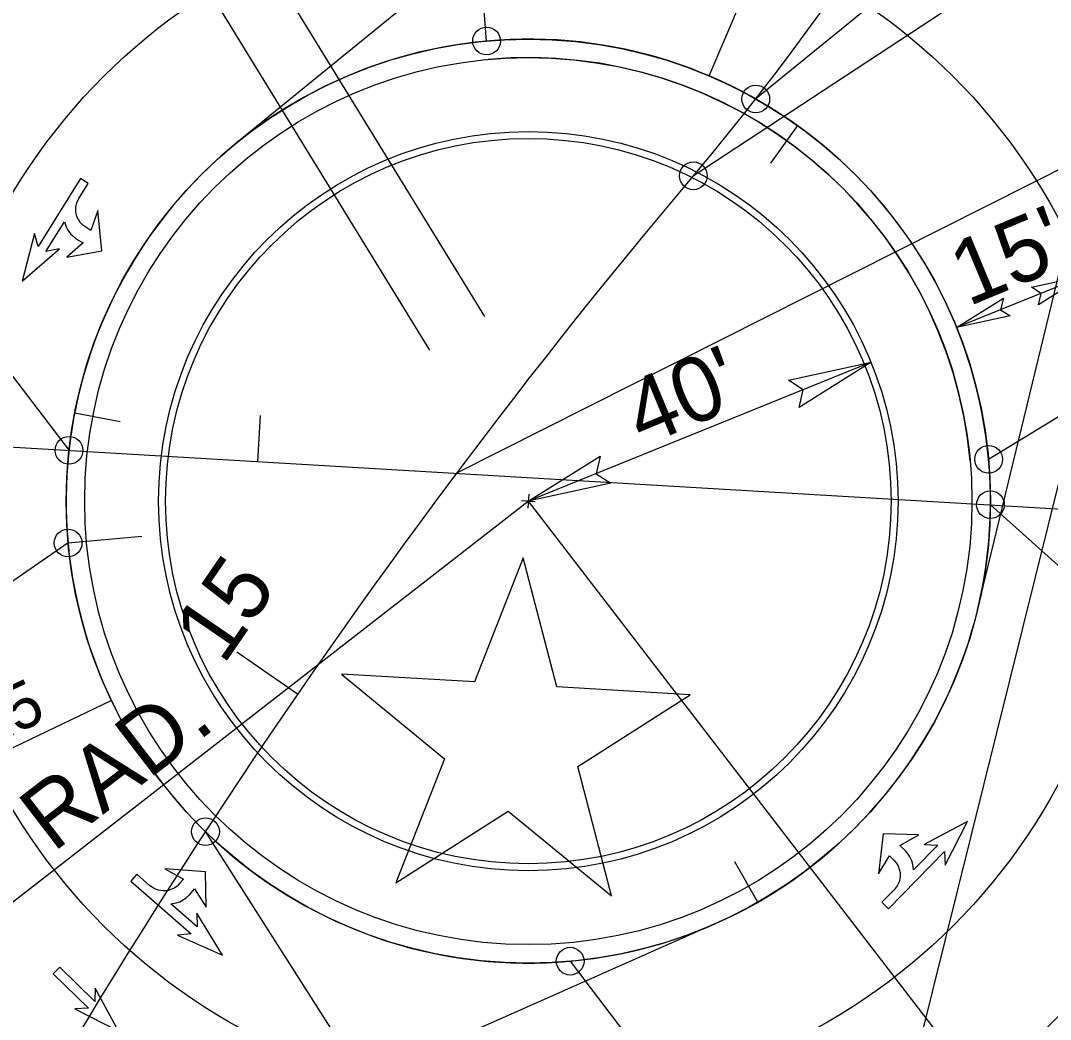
# Model space of a CAD drawing. Extents: x 2010838 to 2015151, y 441905 to 447792.
# Drawn here: x 2011912.5 to 2012023.9, y 444931.1 to 445039.2 of the extents above; entities that cross this region are included whole.
import ezdxf

# ---------------------------------------------------------------- set-up
doc = ezdxf.new("R2010")
doc.units = 0
for name, color, linetype in [('A-Wall-Abov', 7, 'Continuous'), ('A-Wall-Blow', 7, 'Continuous'), ('Block signals', 7, 'Continuous'), ('C-Building', 7, 'Continuous'), ('C-CURB STOPS', 7, 'Continuous'), ('C-EOP 1', 7, 'Continuous'), ('C-Grave Plots', 7, 'Continuous'), ('C-Surface', 7, 'Continuous'), ('CLRD', 7, 'Continuous'), ('Default_10ft_LIDAR_Contou', 7, 'Continuous'), ('Default_2FT_LIDAR_Contour', 7, 'Continuous'), ('HATCH', 7, 'Continuous'), ('s-Existing Major', 7, 'Continuous'), ('S-Existing Minor', 7, 'Continuous'), ('S-overhead electric', 7, 'Continuous'), ('TEXT', 7, 'Continuous'), ('X3', 7, 'Continuous')]:
    doc.layers.add(name, color=color, linetype=linetype)

msp = doc.modelspace()

# ---------------------------------------------------------------- linework, layer by layer
at = {"layer": 'A-Wall-Abov'}
for points in [[(2011919, 445022.07), (2011914.42, 445014.71), (2011914.03, 445016.13), (2011912.69, 445010.98), (2011916.72, 445014.46), (2011915.27, 445014.18), (2011917.26, 445017.38), (2011917.46, 445016.83), (2011917.65, 445016.47), (2011917.94, 445016.1), (2011918.21, 445015.83), (2011918.57, 445015.53), (2011919.29, 445015.12), (2011917.53, 445013.56), (2011921.3, 445014.25), (2011920.89, 445018.63), (2011920.12, 445016.46), (2011919.58, 445016.81), (2011919.26, 445017.03), (2011918.99, 445017.32), (2011918.79, 445017.64), (2011918.61, 445017.98), (2011918.51, 445018.46), (2011918.52, 445018.96), (2011918.63, 445019.44), (2011918.84, 445019.93), (2011919.85, 445021.54)], [(2012006.42, 444943.05), (2012012.49, 444949.23), (2012012.57, 444947.76), (2012014.99, 444952.5), (2012010.3, 444949.98), (2012011.78, 444949.93), (2012009.14, 444947.24), (2012009.07, 444947.82), (2012008.96, 444948.22), (2012008.75, 444948.65), (2012008.54, 444948.96), (2012008.26, 444949.33), (2012007.65, 444949.89), (2012009.7, 444951.03), (2012005.87, 444951.17), (2012005.33, 444946.81), (2012006.54, 444948.76), (2012007, 444948.3), (2012007.26, 444948.02), (2012007.47, 444947.68), (2012007.59, 444947.32), (2012007.69, 444946.95), (2012007.69, 444946.46), (2012007.57, 444945.97), (2012007.36, 444945.53), (2012007.04, 444945.09), (2012005.71, 444943.75)], [(2011924.44, 444946.03), (2011930.97, 444940.33), (2011929.5, 444940.17), (2011934.37, 444938.03), (2011931.58, 444942.56), (2011931.62, 444941.09), (2011928.78, 444943.57), (2011929.36, 444943.67), (2011929.75, 444943.8), (2011930.16, 444944.03), (2011930.46, 444944.26), (2011930.82, 444944.57), (2011931.34, 444945.2), (2011932.6, 444943.22), (2011932.52, 444947.05), (2011928.13, 444947.35), (2011930.15, 444946.24), (2011929.72, 444945.76), (2011929.45, 444945.48), (2011929.13, 444945.26), (2011928.77, 444945.12), (2011928.41, 444944.99), (2011927.92, 444944.97), (2011927.42, 444945.06), (2011926.97, 444945.25), (2011926.52, 444945.53), (2011925.09, 444946.78)], [(2011920.61, 444934.46), (2011920.57, 444932.99), (2011916.76, 444936.71), (2011916.06, 444936), (2011919.87, 444932.27), (2011918.4, 444932.2), (2011923.13, 444929.78)]]:
    msp.add_lwpolyline(points, close=True, dxfattribs=at)
at = {"layer": 'A-Wall-Blow'}
for p, q in [((2011987.02, 445033.18), (2011998.75, 445060.79)), ((2011922.37, 444965.57), (2011895.31, 444952.62))]:
    msp.add_line(p, q, dxfattribs=at)
at = {"layer": 'Block signals'}
for radius in [40, 39.25]:
    msp.add_circle((2011967.46, 444987.16), radius, dxfattribs=at)
at = {"layer": 'C-Building'}
for p, q in [((2011996.58, 445027.81), (2011993.67, 445023.74)), ((2011918.39, 444996.73), (2011923.3, 444995.77)), ((2011938.2, 444991.44), (2011938.49, 444996.43)), ((2011992.31, 444943.77), (2011989.82, 444948.11))]:
    msp.add_line(p, q, dxfattribs=at)
at = {"layer": 'C-CURB STOPS'}
for radius in [48, 40]:
    msp.add_circle((2011967.46, 444987.16), radius, dxfattribs=at)
msp.add_arc((2011967.46, 444987.16), 48, 5.1973, 95.1973, dxfattribs=at)
at = {"layer": 'C-EOP 1'}
for p, q in [((2011917.67, 444982.63), (2011925.64, 444983.36)), ((2011942.5, 444966.26), (2011935.91, 444970.8))]:
    msp.add_line(p, q, dxfattribs=at)
at = {"layer": 'C-Surface'}
for p, q in [((2011984.25, 445065.38), (2011935.86, 445025.91)), ((2012016.06, 444975.4), (2012030.76, 445036.09)), ((2011987.73, 444941.46), (2011933.8, 444917.54))]:
    msp.add_line(p, q, dxfattribs=at)
at = {"layer": 'CLRD'}
msp.add_line((2011239.41, 445032.63), (2013147.4, 444920.16), dxfattribs=at)
for centre, radius, start, end in [((2011767.49, 445206.16), 285, 319.8445, 356.5533), ((2011967.46, 444987.16), 50, 95.1973, 185.1973), ((2011967.46, 444987.16), 50, 5.1973, 95.1973), ((2012535.6, 444558.07), 720, 139.84446, 154.1777), ((2011967.46, 444987.16), 50, 275.1973, 5.1973), ((2011967.46, 444987.16), 50, 185.1973, 275.1973)]:
    msp.add_arc(centre, radius, start, end, dxfattribs=at)
at = {"layer": 'Default_10ft_LIDAR_Contou'}
for p, q in [((2011697.89, 445280.7), (2011917.77, 444992.65)), ((2012172.29, 445177.43), (2011992.07, 445030.69)), ((2011985.31, 445022.37), (2012164.65, 445140.22)), ((2011962.94, 445036.96), (2011955.59, 445132.71)), ((2012163.63, 445093), (2011959.68, 444990.17)), ((2012017.26, 444991.69), (2012152.04, 445074.34)), ((2011967.51, 444987.91), (2011967.42, 444986.41)), ((2011967.46, 444987.16), (2011966.72, 444987.21)), ((2011967.46, 444987.16), (2012057.51, 444870.03)), ((2011967.46, 444987.16), (2011968.21, 444987.12)), ((2012125.28, 444889.75), (2012017.46, 444986.77)), ((2011917.67, 444982.63), (2011806.71, 444906.31)), ((2012044.12, 444776.47), (2011932.53, 444951.39)), ((2011971.99, 444937.37), (2012066.46, 444813.44))]:
    msp.add_line(p, q, dxfattribs=at)
for centre in [(2011962.94, 445036.96), (2011992.07, 445030.69), (2011985.31, 445022.37), (2011917.77, 444992.65), (2012017.26, 444991.69), (2012017.46, 444986.77), (2011917.67, 444982.63), (2011917.67, 444982.63), (2011932.53, 444951.39), (2011971.99, 444937.37)]:
    msp.add_circle(centre, 1.5, dxfattribs=at)
at = {"layer": 'HATCH'}
msp.add_circle((2011967.46, 444987.16), 65, dxfattribs=at)
for start, end in [(77.8866, 152.8308), (242.6645, 336.5135)]:
    msp.add_arc((2011967.46, 444987.16), 80, start, end, dxfattribs=at)
at = {"layer": 's-Existing Major'}
for points in [[(2012021.91, 445010.31), (2012027.71, 445011.57), (2012022.65, 445008.4), (2012022.95, 445009.65)], [(2012019.6, 445007.2), (2012013.8, 445005.94), (2012018.87, 445009.11), (2012018.56, 445007.87)], [(2011995.61, 445000.24), (2012004.54, 445002.19), (2011996.75, 444997.3), (2011997.21, 444999.22)], [(2011976.39, 444989.11), (2011967.46, 444987.16), (2011975.25, 444992.04), (2011974.79, 444990.13)]]:
    msp.add_lwpolyline(points, close=True, dxfattribs=at)
at = {"layer": 'S-Existing Minor'}
for p, q in [((2011915.11, 444547.35), (2012067.43, 445160.54)), ((2012027.71, 445011.57), (2012013.8, 445005.94)), ((2012004.54, 445002.19), (2011967.46, 444987.16)), ((2011904.31, 444938.05), (2011967.46, 444987.16))]:
    msp.add_line(p, q, dxfattribs=at)
at = {"layer": 'S-overhead electric'}
msp.add_circle((2011967.46, 444987.16), 50, dxfattribs=at)
for radius, start, end in [(80, 37.7074, 77.8866), (50, 5.1973, 95.1973), (50, 5.1973, 95.1973), (80, 217.8699, 242.6645)]:
    msp.add_arc((2011967.46, 444987.16), radius, start, end, dxfattribs=at)
at = {"layer": 'TEXT'}
msp.add_lwpolyline([(2011958.4, 444959.27), (2011953.14, 444945.84), (2011965.28, 444953.62), (2011976.45, 444944.45), (2011972.8, 444958.43), (2011984.96, 444966.21), (2011970.56, 444967.06), (2011966.92, 444981.03), (2011961.65, 444967.59), (2011947.23, 444968.44), (2011958.4, 444959.27)], dxfattribs=at)
at = {"layer": 'X3'}
for p, q in [((2011921.98, 445073.52), (2011962.71, 445007.14)), ((2011916.03, 445069.87), (2011956.76, 445003.49))]:
    msp.add_line(p, q, dxfattribs=at)

# ---------------------------------------------------------------- texts
at = {"layer": 'A-Wall-Blow'}
msp.add_text('.025', height=5, rotation=25.5796, dxfattribs=at).set_placement((2011903.74, 444957.98))
at = {"layer": 'C-Grave Plots'}
for s, rotation, p in [("15'", 22.5868, (2012015.05, 445008.19)), ("40'", 22.5868, (2011979.81, 444993.04)), ("80' RAD.", 37.5249, (2011904.31, 444940.05))]:
    msp.add_text(s, height=7, rotation=rotation, dxfattribs=at).set_placement(p)
at = {"layer": 'Default_2FT_LIDAR_Contour'}
msp.add_text('15', height=7, rotation=55.4631, dxfattribs=at).set_placement((2011934.46, 444969.32))

doc.saveas('drawing.dxf')
